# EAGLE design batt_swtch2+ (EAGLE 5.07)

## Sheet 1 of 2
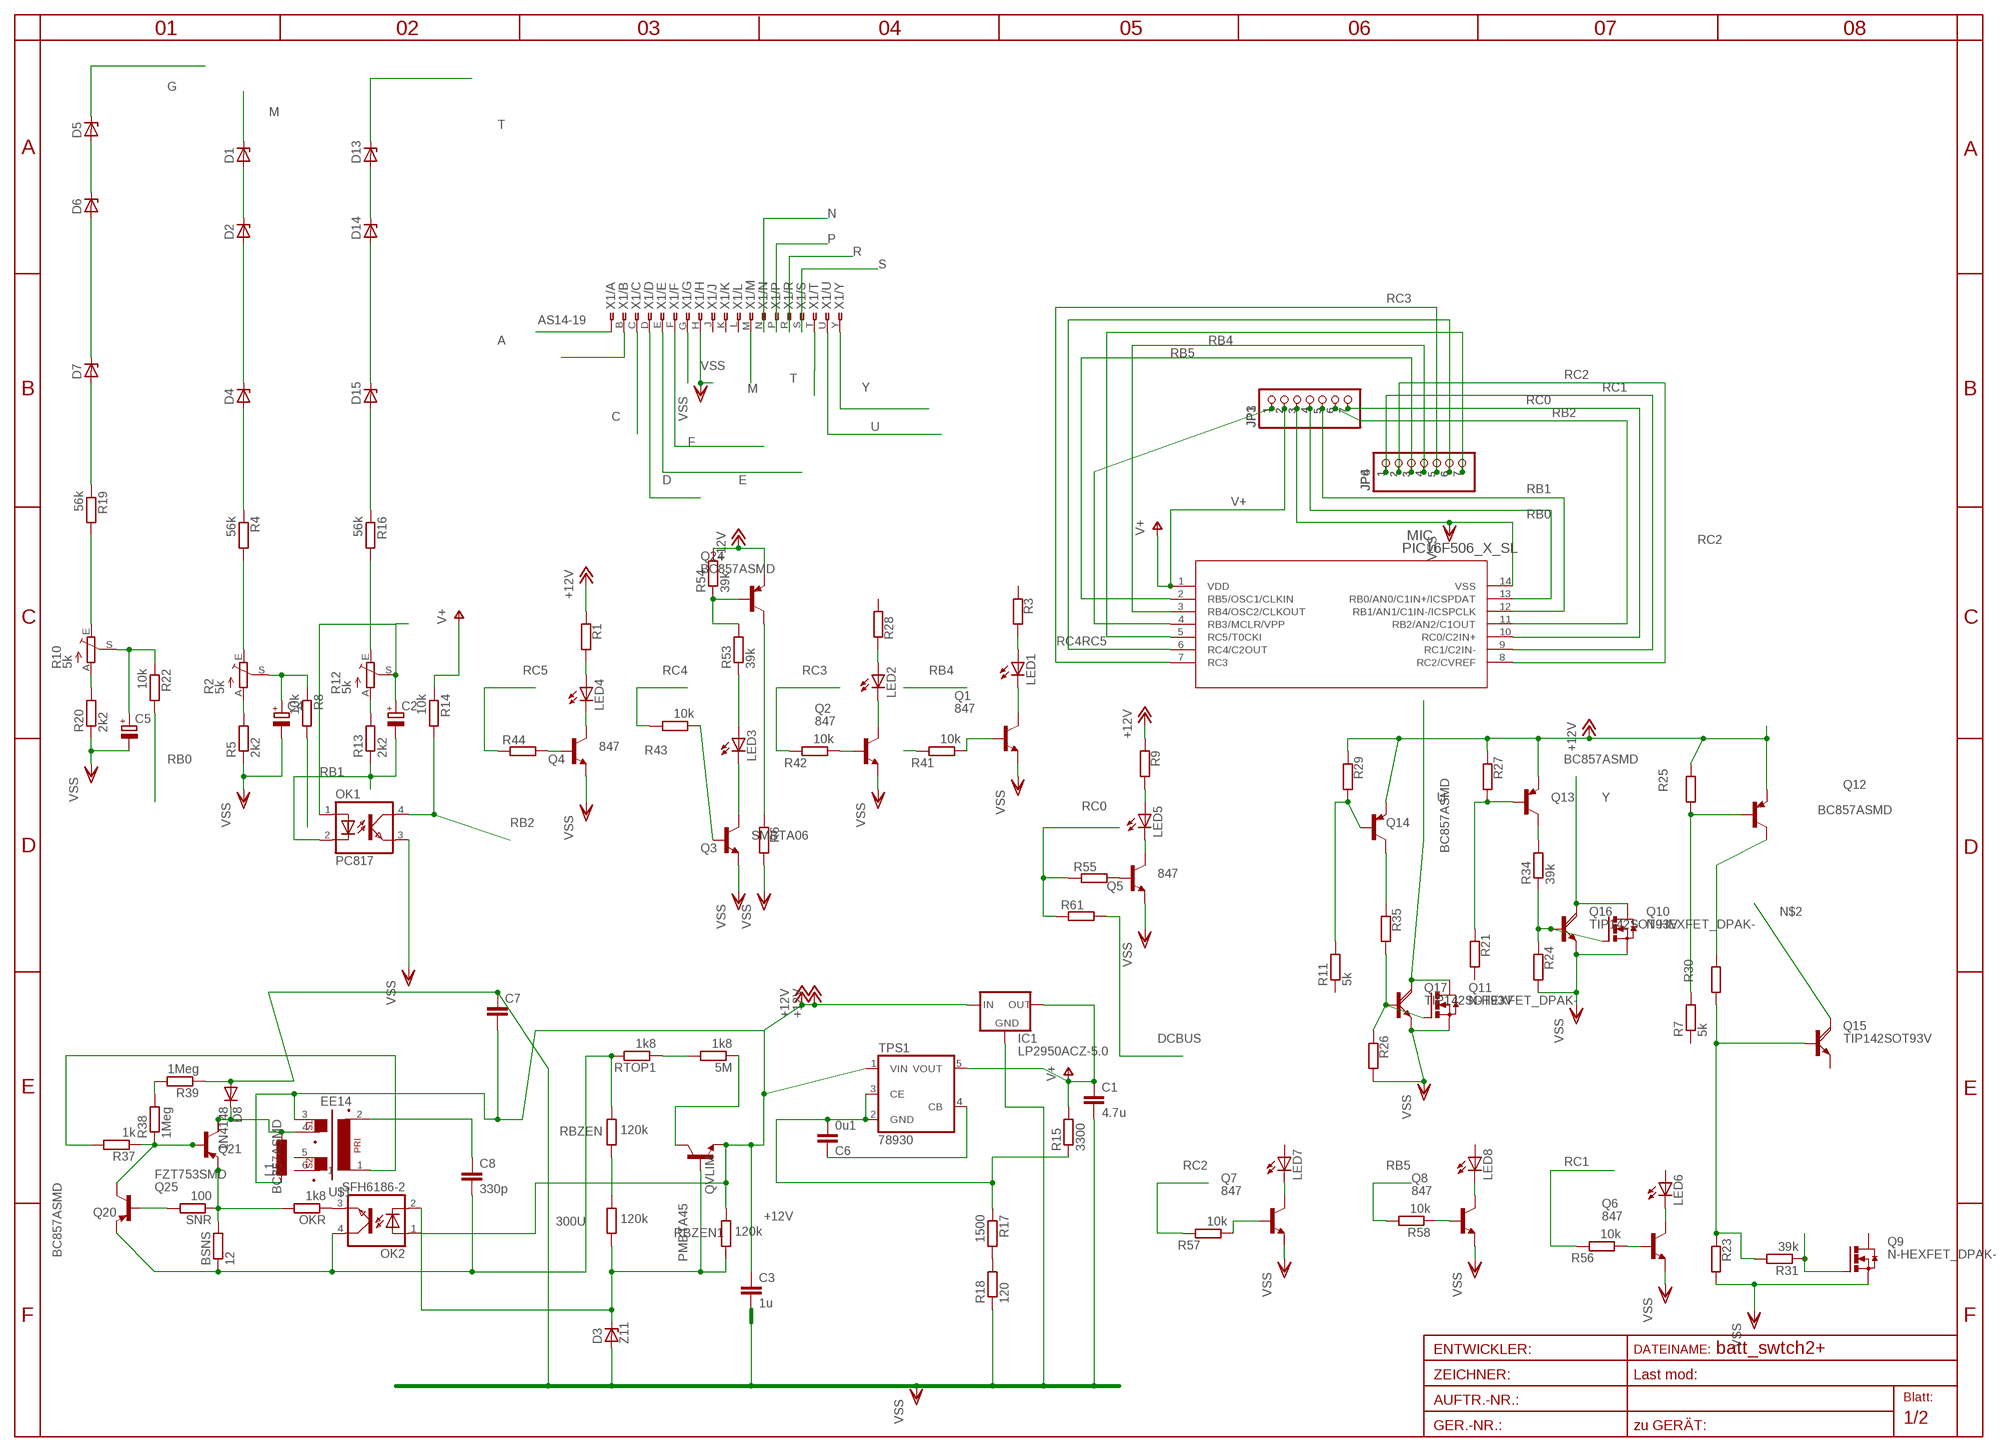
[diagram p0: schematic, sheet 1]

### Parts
5M  1k8  R-EU_R1206  [R1206]
300U  120k  R-EU_R1206  [R1206]
BSNS  12  R-EU_R0805  [R0805]
C1  4.7u  C-EUC1206  [C1206]
C2  CPOL-EUE2,5-6E  [E2,5-6E]
C3  1u  C-EUC1206  [C1206]
C4  CPOL-EUE2,5-6E  [E2,5-6E]
C5  CPOL-EUE2,5-6E  [E2,5-6E]
C6  0u1  C-EUC0805  [C0805]
C7  C-EU025-025X050  [C025-025X050]
C8  330p  C-EUC0805  [C0805]
D1  ZENER-DIODESOD80C  [SOD80C]
D2  ZENER-DIODESOD80C  [SOD80C]
D3  Z11  ZENER-DIODESOD80C  [SOD80C]
D4  ZENER-DIODESOD80C  [SOD80C]
D5  ZENER-DIODESOD80C  [SOD80C]
D6  ZENER-DIODESOD80C  [SOD80C]
D7  ZENER-DIODESOD80C  [SOD80C]
D8  1N4148  DIODE-SMA-DO214  [SMA-DO214AC]
D13  ZENER-DIODESOD80C  [SOD80C]
D14  ZENER-DIODESOD80C  [SOD80C]
D15  ZENER-DIODESOD80C  [SOD80C]
IC1  LP2950ACZ-5.0  [TO92]
JP1  PINHD-1X7  [1X07]
JP3  PINHD-1X7  [1X07]
JP4  PINHD-1X7  [1X07]
JP6  PINHD-1X7  [1X07]
L1  L-EU0204/5  [0204/5]
LED1  LEDCHIPLED_1206  [CHIPLED_1206]
LED2  LEDCHIPLED_1206  [CHIPLED_1206]
LED3  LEDCHIPLED_1206  [CHIPLED_1206]
LED4  LEDCHIPLED_1206  [CHIPLED_1206]
LED5  LEDCHIPLED_1206  [CHIPLED_1206]
LED6  LEDCHIPLED_1206  [CHIPLED_1206]
LED7  LEDCHIPLED_1206  [CHIPLED_1206]
LED8  LEDCHIPLED_1206  [CHIPLED_1206]
MIC  PIC16F506_X_SL  [SOIC14_N_MC]
OK1  PC817  [DIL04]
OK2  SFH6186-2  [SMD4]
OKR  1k8  R-EU_R0805  [R0805]
Q1  847  BC847ASMD  [SOT23]
Q2  847  BC847ASMD  [SOT23]
Q3  SMBTA06  BC847ASMD  [SOT23]
Q4  847  BC847ASMD  [SOT23]
Q5  847  BC847ASMD  [SOT23]
Q6  847  BC847ASMD  [SOT23]
Q7  847  BC847ASMD  [SOT23]
Q8  847  BC847ASMD  [SOT23]
Q9  N-HEXFET_DPAK-  [TO252]
Q10  N-HEXFET_DPAK-  [TO252]
Q11  N-HEXFET_DPAK-  [TO252]
Q12  BC857ASMD  [SOT23-BEC]
Q13  BC857ASMD  [SOT23-BEC]
Q14  BC857ASMD  [SOT23-BEC]
Q15  TIP142SOT93V  [SOT93V]
Q16  TIP142SOT93V  [SOT93V]
Q17  TIP142SOT93V  [SOT93V]
Q20  BC857ASMD  [SOT23-BEC]
Q21  BC857ASMD  [SOT23-BEC]
Q24  BC857ASMD  [SOT23-BEC]
Q25  FZT753SMD  [SOT223]
QVLIM  PMBTA45  BC847ALT1SMD  [SOT23]
R1  39k  R-EU_R0805  [R0805]
R2  5k  TRIM_EU-S64W  [S64W]
R3  39k  R-EU_R0805  [R0805]
R4  56k  R-EU_R0805  [R0805]
R5  2k2  R-EU_R0805  [R0805]
R6  39k  R-EU_R0805  [R0805]
R7  5k  R-EU_R0805  [R0805]
R8  10k  R-EU_R0805  [R0805]
R9  5k  R-EU_R0805  [R0805]
R10  5k  TRIM_EU-S64W  [S64W]
R11  5k  R-EU_R0805  [R0805]
R12  5k  TRIM_EU-S64W  [S64W]
R13  2k2  R-EU_R0805  [R0805]
R14  10k  R-EU_R0805  [R0805]
R15  3300  R-EU_R0805  [R0805]
R16  56k  R-EU_R0805  [R0805]
R17  1500  R-EU_R0805  [R0805]
R18  120  R-EU_R0805  [R0805]
R19  56k  R-EU_R0805  [R0805]
R20  2k2  R-EU_R0805  [R0805]
R21  5k  R-EU_R0805  [R0805]
R22  10k  R-EU_R0805  [R0805]
R23  39k  R-EU_R0805  [R0805]
R24  39k  R-EU_R0805  [R0805]
R25  39k  R-EU_R0805  [R0805]
R26  39k  R-EU_R0805  [R0805]
R27  39k  R-EU_R0805  [R0805]
R28  39k  R-EU_R0805  [R0805]
R29  39k  R-EU_R0805  [R0805]
R30  39k  R-EU_R0805  [R0805]
R31  39k  R-EU_R0805  [R0805]
R34  39k  R-EU_R0805  [R0805]
R35  39k  R-EU_R0805  [R0805]
R37  1k  R-EU_R0805  [R0805]
R38  1Meg  R-EU_R1206  [R1206]
R39  1Meg  R-EU_R1206  [R1206]
R41  10k  R-EU_R0805  [R0805]
R42  10k  R-EU_R0805  [R0805]
R43  10k  R-EU_R0805  [R0805]
R44  10k  R-EU_R0805  [R0805]
R53  39k  R-EU_R0805  [R0805]
R54  39k  R-EU_R0805  [R0805]
R55  10k  R-EU_R0805  [R0805]
R56  10k  R-EU_R0805  [R0805]
R57  10k  R-EU_R0805  [R0805]
R58  10k  R-EU_R0805  [R0805]
R61  10k  R-EU_R0805  [R0805]
RBZEN  120k  R-EU_R1206  [R1206]
RBZEN1  120k  R-EU_R0805  [R0805]
RTOP1  1k8  R-EU_R1206  [R1206]
SNR  100  R-EU_R1206  [R1206]
TPS1  78930  TPS78930SOT23-5  [SOT25]
U$1  EE14  [EE14]
X1  AS14-19  AS14-19OLIVE  [Y28M-19TK]

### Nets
+12V: C3.1 C7.2 IC1.3(IN) L1.2 OK2.1(A) Q12.E Q13.E Q14.E Q24.E QVLIM.2(E) R1.2 R9.2 R25.2 R27.2 R29.2 R54.2 RBZEN1.1 TPS1.1(VIN) U$1.3
A: X1.A ; also sheet 2
B1C2: Q20.C Q21.B Q25.1(B) R37.1 R38.1
BOOST_EN: Q24.C R6.2 ; also sheet 2
C: X1.C
C1: D8.K(C) L1.1 Q21.C Q25.2(C) U$1.4
CB: 300U.2 D3.C OK2.2(C) QVLIM.1(B) RBZEN1.2
D: X1.D
DCBUS: R61.1 ; also sheet 2
E: X1.E
EB: BSNS.2 OKR.2 Q21.E Q25.3(E) SNR.1
F: X1.F
G: BSNS.1 C8.2 D5.C OK2.4(COL) Q20.E RBZEN.1 RTOP1.2 X1.G ; also sheet 2
GND1: C6.1 TPS1.4(CB)
M: D1.C X1.M
N: X1.N
N$1: 300U.1 RBZEN.2
N$2: Q15.C
N$3: OK2.3(EMIT) OKR.1
N$4: Q8.1(B) R58.1
N$5: C2.+ OK1.1(A) R12.S
N$6: Q3.1(B) R43.1
N$7: LED6.C Q6.3(C)
N$8: R17.2 R18.2
N$9: R41.2
N$10: LED8.C Q8.3(C)
N$11: Q2.1(B) R42.1
N$12: Q1.1(B) R41.1
N$14: Q5.1(B) R55.1
N$16: 5M.1 QVLIM.3(C)
N$17: LED7.C Q7.3(C)
N$18: D15.A R16.1
N$19: LED1.C Q1.3(C)
N$20: LED1.A R3.1
N$21: Q14.B R11.2 R29.1
N$22: LED2.C Q2.3(C)
N$23: D14.A D15.C
N$24: D13.A D14.C
N$25: LED2.A R28.1
N$26: R12.A R13.2
N$28: Q6.1(B) R56.1
N$29: 5M.2 RTOP1.1
N$30: Q4.1(B) R44.1
N$31: Q7.1(B) R57.1
N$32: LED3.C Q3.3(C)
N$33: LED4.C Q4.3(C)
N$34: D7.A R19.1
N$35: D6.A D7.C
N$36: LED4.A R1.1
N$37: Q12.C R30.2
N$38: D5.A D6.C
N$39: R10.E R19.2
N$40: R10.A R20.2
N$41: D4.A R4.1
N$42: D2.A D4.C
N$43: D1.A D2.C
N$44: R2.E R4.2
N$45: R2.A R5.2
N$46: C4.+ R2.S R8.1
N$47: LED5.A R9.1
N$48: C5.+ R10.S R22.1
N$49: Q14.C R35.2
N$50: Q15.B R23.2 R30.1 R31.2
N$51: Q10.1(G) Q16.B R24.2 R34.1
N$52: LED5.C Q5.3(C)
N$53: Q12.B R7.2 R25.1
N$54: Q9.1(G) R31.1
N$55: Q13.B R21.2 R27.1
N$57: Q13.C R34.2
N$59: Q11.1(G) Q17.B R26.2 R35.1
N$60: R37.2 U$1.1
N$61: C8.1 U$1.2
N$62: R38.2 R39.2
N$63: Q20.B SNR.2
N$65: R12.E R16.2
N$81: Q24.B R53.2 R54.1
N$82: LED3.A R53.1
P: X1.P
R: X1.R
RB0: JP1.4 JP3.4 MIC.13(RB0/AN0/C1IN+/ICSPDAT) R22.2
RB1: JP1.5 JP3.5 MIC.12(RB1/AN1/C1IN-/ICSPCLK) R8.2
RB2: JP1.6 JP3.6 MIC.11(RB2/AN2/C1OUT) OK1.4(COL) R14.2
RB4: JP4.4 JP6.4 MIC.3(RB4/OSC2/CLKOUT)
RB5: JP4.3 JP6.3 MIC.2(RB5/OSC1/CLKIN) R58.2
RC0: JP1.7 JP3.7 MIC.10(RC0/C2IN+) R55.2 R61.2
RC1: JP4.1 JP6.1 MIC.9(RC1/C2IN-) R56.2
RC2: JP4.2 JP6.2 MIC.8(RC2/CVREF) R57.2
RC3: JP4.5 JP6.5 MIC.7(RC3) R42.2
RC4: JP4.6 JP6.6 MIC.6(RC4/C2OUT) R43.2
RC5: JP4.7 JP6.7 MIC.5(RC5/T0CKI) R44.2
S: C2.- OK1.2(C) R13.1 X1.S
T: D13.C X1.T
U: Q11.3(D) Q17.C X1.U
V+: C1.1 IC1.1(OUT) JP1.2 JP3.2 MIC.1(VDD) R14.1 R15.2 TPS1.5(VOUT)
V-: C6.2 R15.1 R17.1 TPS1.2(GND) TPS1.3(CE)
VSS: C1.2 C3.2 C4.- C5.- C7.1 D3.A D8.A IC1.2(GND) JP1.3 JP3.3 MIC.14(VSS) OK1.3(EMIT) Q1.2(E) Q2.2(E) Q3.2(E) Q4.2(E) Q5.2(E) Q6.2(E) Q7.2(E) Q8.2(E) Q9.2(S) Q10.2(S) Q11.2(S) Q16.E Q17.E R5.1 R6.1 R18.1 R20.1 R23.1 R24.1 R26.1 R39.1 X1.B X1.H ; also sheet 2
WIND: JP1.1 JP3.1 MIC.4(RB3/MCLR/VPP)
Y: Q10.3(D) Q16.C X1.Y
Unconnected: LED6.A LED7.A LED8.A Q9.3(D) Q15.E Q25.4(C/) R3.2 R7.1 R11.1 R21.1 R28.2 U$1.5 U$1.6 X1.J X1.K X1.L

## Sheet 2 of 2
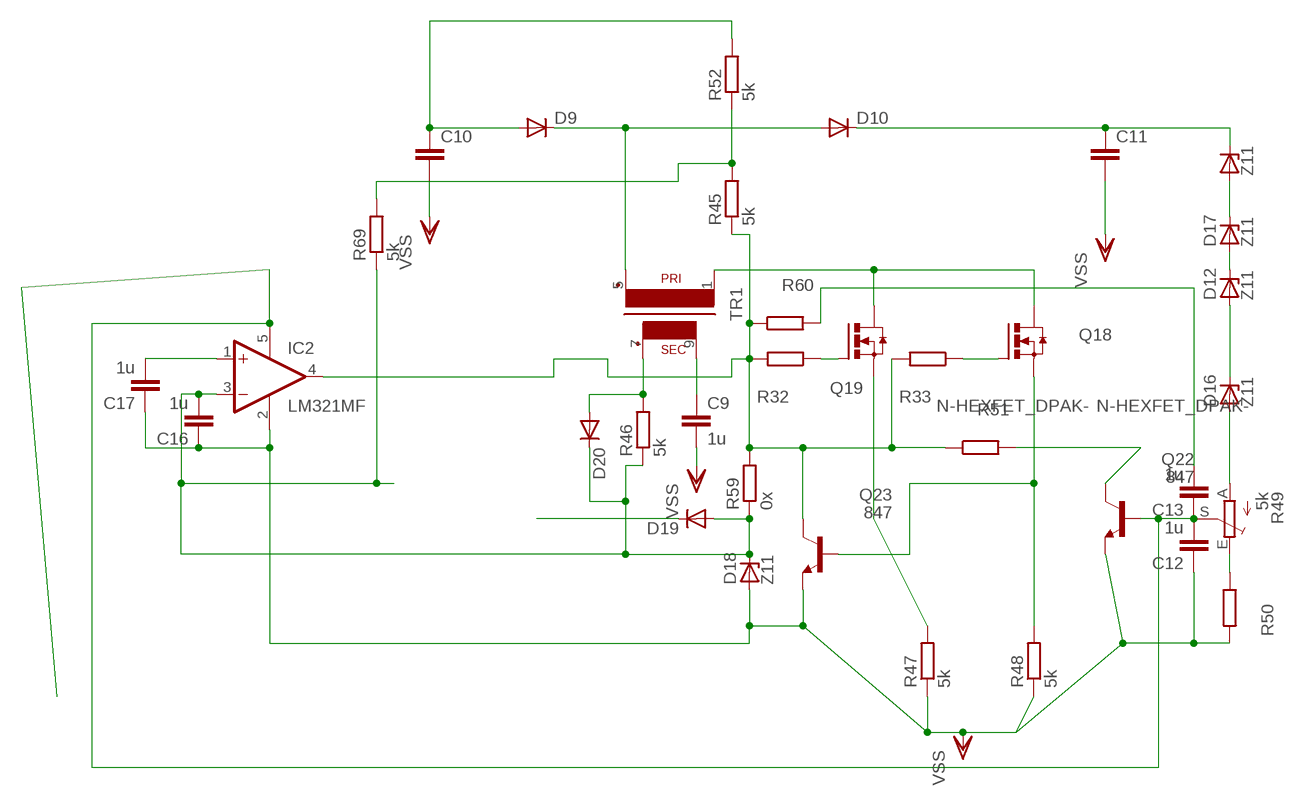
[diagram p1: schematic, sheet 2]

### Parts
C9  1u  C-EUC1206  [C1206]
C10  C-EU075-052X106  [C075-052X106]
C11  C-EU075-052X106  [C075-052X106]
C12  1u  C-EUC1206  [C1206]
C13  1u  C-EUC1206  [C1206]
C16  1u  C-EUC0805  [C0805]
C17  1u  C-EUC0805  [C0805]
D9  DIODE-SMC  [SMC]
D10  DIODE-SMC  [SMC]
D11  Z11  ZENER-DIODESOD80C  [SOD80C]
D12  Z11  ZENER-DIODESOD80C  [SOD80C]
D16  Z11  ZENER-DIODESOD80C  [SOD80C]
D17  Z11  ZENER-DIODESOD80C  [SOD80C]
D18  Z11  ZENER-DIODESOD80C  [SOD80C]
D19  DIODE-MINIMELF  [MINIMELF]
D20  DIODE-MINIMELF  [MINIMELF]
IC2  LM321MF  [SOT23-5]
Q18  N-HEXFET_DPAK-  [TO252]
Q19  N-HEXFET_DPAK-  [TO252]
Q22  847  BC847ASMD  [SOT23]
Q23  847  BC847ASMD  [SOT23]
R32  39k  R-EU_R0805  [R0805]
R33  39k  R-EU_R0805  [R0805]
R45  5k  R-EU_R1206  [R1206]
R46  5k  R-EU_R0805  [R0805]
R47  5k  R-EU_R2010  [R2010]
R48  5k  R-EU_R2010  [R2010]
R49  5k  TRIM_EU-S64W  [S64W]
R50  39k  R-EU_R0805  [R0805]
R51  39k  R-EU_R0805  [R0805]
R52  5k  R-EU_R1206  [R1206]
R59  0x  R-EU_R0402  [R0402]
R60  39k  R-EU_R0805  [R0805]
R69  5k  R-EU_0207/22  [0207/22]
TR1  VR11  [1X3WDIRVER]

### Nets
A: C11.1 D10.C D11.C ; also sheet 1
BOOST_EN: D19.C ; also sheet 1
DCBUS: C12.2 C13.1 IC2.5(V+) Q22.1(B) R49.S ; also sheet 1
G: C10.1 D9.A R52.2 ; also sheet 1
N$13: D9.C D10.A TR1.5(P2)
N$15: Q18.3(D) Q19.3(D) TR1.1
N$27: C16.2 D18.C D19.A D20.C IC2.3(-IN) R46.1 R59.1 R69.1
N$56: Q18.1(G) R33.1
N$58: Q19.1(G) R32.1
N$64: D20.A R46.2 TR1.7(S3)
N$66: IC2.4(OUT) Q23.3(C) R32.2 R33.2 R45.1 R51.1 R59.2 R60.1
N$67: C13.2 R60.2
N$68: Q19.2(S) R47.2
N$71: Q22.3(C) R51.2
N$72: Q18.2(S) Q23.1(B) R48.2
N$73: D16.A R49.A
N$74: C9.1 TR1.9(S4)
N$76: D12.A D16.C
N$77: D12.C D17.A
N$78: R49.E R50.1
N$79: D11.A D17.C
N$80: R45.2 R52.1 R69.2
N$96: C17.2 IC2.1(+IN)
VSS: C9.2 C10.2 C11.2 C12.1 C16.1 C17.1 D18.A IC2.2(V-) Q22.2(E) Q23.2(E) R47.1 R48.1 R50.2 ; also sheet 1

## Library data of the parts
5M 300U BSNS OKR R4 R5 R8 R13-R20 R22 R37-R39 RBZEN RBZEN1 RTOP1 SNR = rcl:R-EU_: RESISTOR, European symbol
C1 C3 C6-C13 C16 C17 = rcl:C-EU: CAPACITOR, European symbol
C2 C4 C5 = rcl:CPOL-EU: POLARIZED CAPACITOR, European symbol
D1-D7 D11-D18 = diode:ZENER-DIODE: Z-Diode
D8-D10 D19 D20 = diode:DIODE-: DIODE
IC1 = v-reg:LP2950?*: Source: http://cache.national.com/ds/LP/LP2950.pdf
IC2 = linear:LM321?*: Low Power Single Op Amp Source: http://cache.national.com/ds/LM/LM321.pdf
JP1 JP3 JP4 JP6 = pinhead:PINHD-1X7: PIN HEADER
L1 = rcl:L-EU: INDUCTOR, European symbol
LED1-LED8 = led:LED: LED
MIC = pic16f506mc:PIC16F506_X_SL
OK1 = optocoupler:PC817: SHARP OPTO COUPLER
OK2 = optocoupler:SFH618?*: Optocoupler, Phototransistor Output, Low Input Current Source: http://www.vishay.com/docs/83673/sfh618.pdf
Q1-Q8 Q22 Q23 QVLIM = transistor-npn:BC847*: NPN Transistor
Q9-Q11 Q18 Q19 = transistor-power:N-HEXFET_?-*: HEXFET® Power MOSFET
Q12-Q14 Q20 Q21 Q24 = transistor-pnp:BC857*: PNP Transistror
Q15-Q17 = transistor-power:TIP142: NPN DARLINGTON TRANSISTOR
Q25 = transistor-pnp:FZT753SMD: PNP Transistor
R1 R3 R6 R7 R9 R11 R21 R23-R35 R41-R48 R50-R61 R69 = rcl-2:R-EU_: RESISTOR, European symbol
R2 R10 R12 R49 = pot:TRIM_EU-: POTENTIOMETER
TPS1 = v-reg:TPS78930
TR1 = trafo:VR11: TRANSFORMER 1 primary winding, 1 secondary winding BLOCK
U$1 = trafo:EE14
X1 = con-deutsch:AS14-19: DEUTSCH Connector

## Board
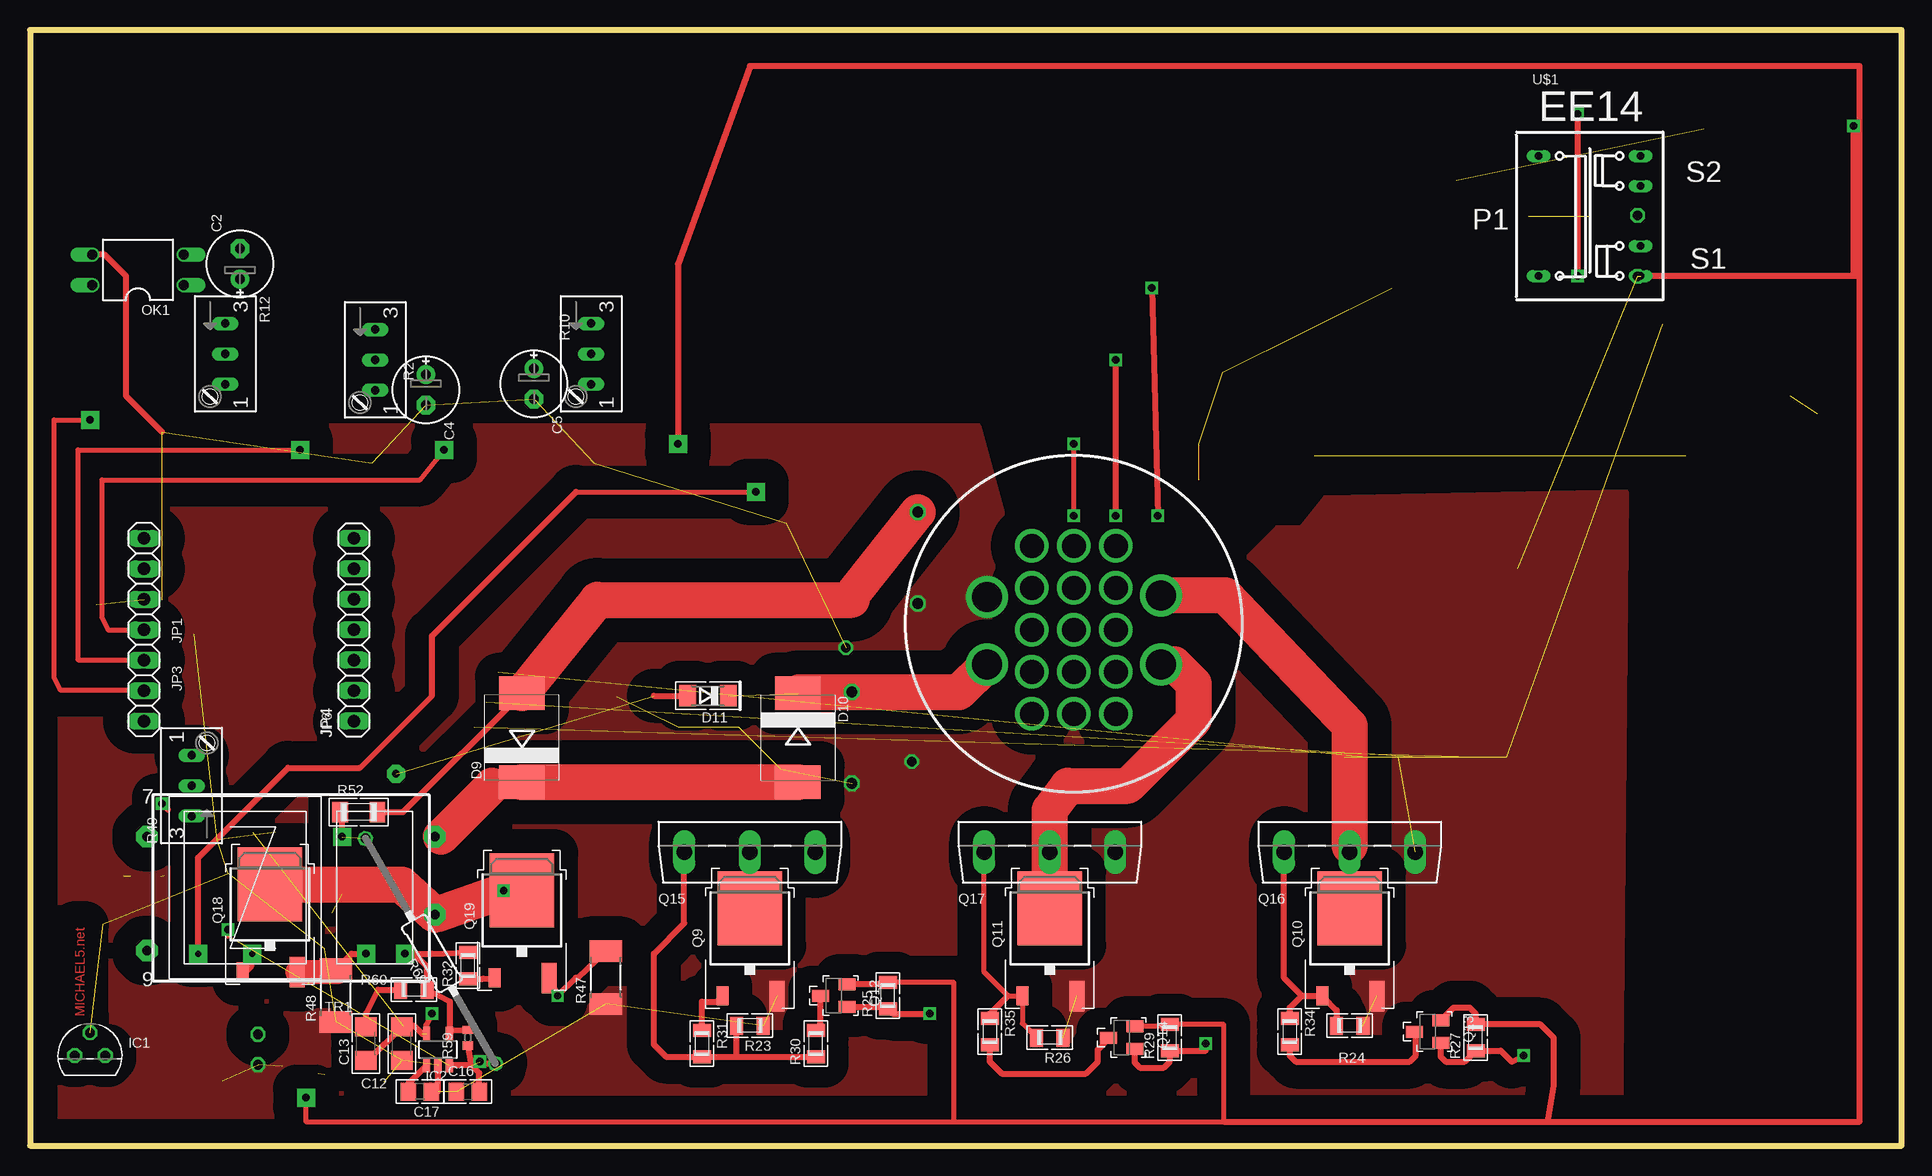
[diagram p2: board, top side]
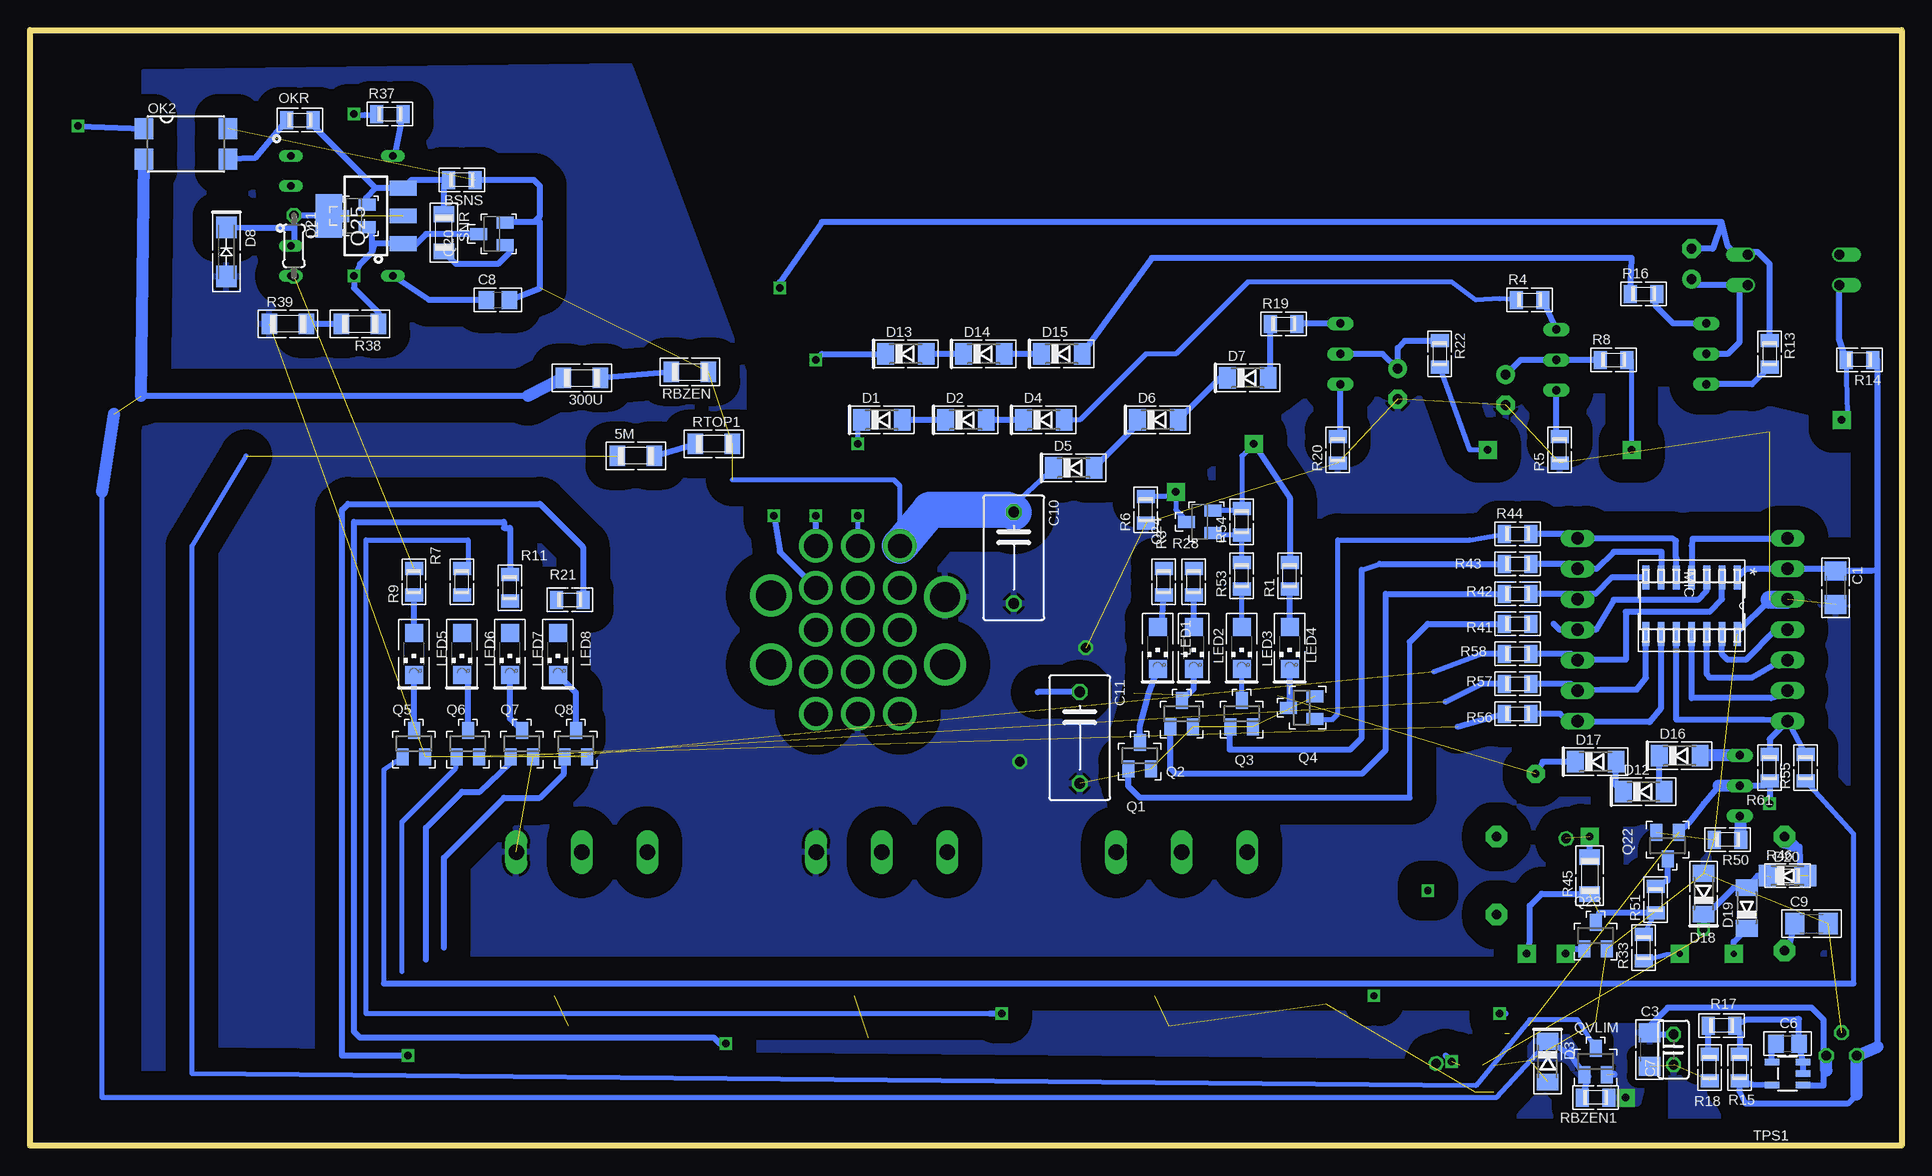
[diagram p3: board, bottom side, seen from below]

Size 156 x 93 mm. Coordinates in mm from the lower left corner, seen from the top.
Outline: 156,0 156,93 0,93 0,0 156,0
Copper layers (1*16): Top 0.035mm / dielectric 1.5mm / Bottom 0.035mm
Design rules "default *": minimum track width 40mil, minimum drill 30mil, track to track 8mil, track to pad 8mil, pad to pad 8mil, via to via 8mil, smd to smd 8mil, copper to edge 40mil, drill to drill 8mil, minimum pad ring 8mil, minimum via ring 8mil, stop-mask expansion 4mil, vias tented up to drill 0mil, thermal gap 10mil

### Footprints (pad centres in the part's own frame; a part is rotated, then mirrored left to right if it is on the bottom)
R1206 = smd 1.3 x 1.7: 1 -1.55,0; 2 1.55,0
R0805 = smd 1.1 x 1.5: 1 -1.1,0; 2 1.1,0
C1206 = smd 1.6 x 1.8: 1 -1.4,0; 2 1.4,0
E2,5-6E = drill 0.813 pad 1.575 round: + -1.27,0 | drill 0.813 pad 1.575 octagon: - 1.27,0
C0805 = smd 1.3 x 1.5: 1 -0.95,0; 2 0.95,0
C025-025X050 = drill 0.813 octagon: 1 -1.27,0; 2 1.27,0
C075-052X106 = drill 0.914 octagon: 1 -3.81,0; 2 3.81,0
SOD80C = smd 1.4 x 1.8: A 1.7,0; C -1.7,0
SMA-DO214AC = smd 1.8 x 1.7: A 2.05,-0.127; K -2.05,-0.127
SMC = smd 2.8 x 3.8: A 3.7,0; C -3.7,0
MINIMELF = smd 1.4 x 1.8: A 1.7,0; C -1.7,0
TO92 = drill 0.813 octagon: 1 -1.27,0; 2 0,1.905; 3 1.27,0
SOT23-5 = smd 0.6 x 1.2: 1 -0.95,-1.306; 2 0,-1.306; 3 0.95,-1.306; 4 0.95,1.306; 5 -0.95,1.306
1X07 = drill 1.016 long: 1 -7.62,0; 2 -5.08,0; 3 -2.54,0; 4 0,0; 5 2.54,0; 6 5.08,0; 7 7.62,0
0204/5 = drill 0.813 octagon: 1 -2.54,0; 2 2.54,0
CHIPLED_1206 = smd 1.5 x 1.5: A 0,-1.75; C 0,1.75
SOIC14_N_MC = smd 1.981 x 0.559: 1 -2.362,3.81; 2 -2.362,2.54; 3 -2.362,1.27; 4 -2.362,0; 5 -2.362,-1.27; 6 -2.362,-2.54; 7 -2.362,-3.81; 8 2.362,-3.81; 9 2.362,-2.54; 10 2.362,-1.27; 11 2.362,0; 12 2.362,1.27; 13 2.362,2.54; 14 2.362,3.81
DIL04 = drill 0.813 offset: 1 -1.27,-3.81; 2 1.27,-3.81; 3 1.27,3.81; 4 -1.27,3.81
SMD4 = smd 1.78 x 1.55: 1 -1.27,-3.5; 2 1.27,-3.5; 3 1.27,3.5; 4 -1.27,3.5
SOT23 = smd 1 x 1.4: 1 -0.95,-1.1; 2 0.95,-1.1; 3 0,1.1
TO252 = smd 1 x 1.6: 1 -2.28,-3.53 | smd 1.27 x 2.54: 2 2.28,-3.53 | smd 5.4 x 6.2: 3 0,3.77
SOT23-BEC = smd 1 x 1.4: B -0.95,-1.1; C 0,1.1; E 0.95,-1.1
SOT93V = drill 1.3 pad 1.676 long: B -5.461,-2.54; C 0,-2.54; E 5.461,-2.54
SOT223 = smd 1.219 x 2.235: 1 -2.311,-3.099; 2 0,-3.099; 3 2.311,-3.099 | smd 3.6 x 2.2: 4 0,3.099
S64W = drill 0.7 long: A 2.54,1.27; E -2.54,1.27; S 0,1.27
R2010 = smd 1.8 x 2.7: 1 -2.2,0; 2 2.2,0
R0402 = smd 0.7 x 0.9: 1 -0.65,0; 2 0.65,0
0207/22 = drill 0.813 octagon: 1 -10.58,0; 2 11.08,0
SOT25 = smd 0.55 x 1.2: 1 -0.95,-1.3; 2 0,-1.3; 3 0.95,-1.3; 4 0.95,1.3; 5 -0.95,1.3
1X3WDIRVER = drill 0.8 pad 1.778 octagon: 1 -12,2.25; 5 -12,-4.25; 7 12,-4.25; 9 12,5.25
EE14 = drill 0.6 pad 1 long: 1 4.25,-5; 2 4.25,5; 3 -4.25,5 | drill 0.6 pad 1.016 long: 4 -4.25,2.5; 5 -4.25,-2.5; 6 -4.25,-5
Y28M-19TK = drill 2.5 pad 3.5 round: A -7.25,-2.875; B -7.25,2.75; U 7.25,-2.875; Y 7.25,2.875 | drill 2 pad 2.54 round: C -3.5,-7; D -3.5,-3.5; E -3.5,0; F -3.5,3.5; G -3.5,7; H 0,-7; J 0,-3.5; K 0,0; L 0,3.5; M 0,7; N 3.5,-7; P 3.5,-3.5; R 3.5,0; S 3.5,3.5; T 3.5,7

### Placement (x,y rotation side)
5M  105.5,57.5 0 bottom
300U  110,64 180 bottom
BSNS  120,80.5 180 bottom
C1  5.5,46.5 270 bottom
C2  17.5,73.5 90 top
C3  21,8 270 bottom
C4  33,63 270 top
C5  42,63.5 270 top
C6  9.5,8.5 0 bottom
C7  19,8 90 bottom
C8  117,70.5 0 bottom
C9  7.5,18.5 0 bottom
C10  74,49 270 bottom
C11  68.5,34 270 bottom
C12  31,8.5 90 top
C13  28,8.5 90 top
C16  36.5,4.5 0 top
C17  32.5,4.5 180 top
D1  85,60.5 0 bottom
D2  78,60.5 0 bottom
D3  29.5,7 270 bottom
D4  71.5,60.5 0 bottom
D5  69,56.5 0 bottom
D6  62,60.5 0 bottom
D7  54.5,64 0 bottom
D8  139.5,74.5 270 bottom
D9  41,34 90 top
D10  64,34 270 top
D11  56.5,37.5 180 top
D12  21.5,29.5 0 bottom
D13  83,66 0 bottom
D14  76.5,66 0 bottom
D15  70,66 0 bottom
D16  18.5,32.5 0 bottom
D17  25.5,32 0 bottom
D18  16.5,21 90 bottom
D19  12.9,19.8 90 bottom
D20  9.5,22.5 0 bottom
IC1  5,7.5 0 top
IC2  34,8 0 top
JP1  9.5,43 270 top
JP3  9.5,43 270 top
JP4  27,43 90 top
JP6  27,43 90 top
L1  134,75 270 bottom
LED1  62,41.5 180 bottom
LED2  59,41.5 180 bottom
LED3  55,41.5 180 bottom
LED4  51,41.5 180 bottom
LED5  124,41 180 bottom
LED6  120,41 180 bottom
LED7  116,41 180 bottom
LED8  112,41 180 bottom
MIC  17.5,45 270 bottom
OK1  9,73 90 top
OK2  143,83.5 270 bottom
OKR  133.5,85.5 0 bottom
Q1  63.5,32.5 0 bottom
Q2  60,36 0 bottom
Q3  55,36 0 bottom
Q4  50,36.5 90 bottom
Q5  124,33.5 0 bottom
Q6  119.5,33.5 0 bottom
Q7  115,33.5 0 bottom
Q8  110.5,33.5 0 bottom
Q9  60,16 0 top
Q10  110,16 0 top
Q11  85,16 0 top
Q12  67,12.5 90 top
Q13  116.5,9.5 90 top
Q14  91,9 90 top
Q15  60,27 0 top
Q16  110,27 0 top
Q17  85,27 0 top
Q18  20,18 0 top
Q19  41,17.5 0 top
Q20  117.5,76 90 bottom
Q21  129,77.5 90 bottom
Q22  19.5,25 180 bottom
Q23  25.5,17.5 0 bottom
Q24  58.5,52 90 bottom
Q25  128,77.5 90 bottom
QVLIM  25.5,7 0 bottom
R1  51,47.5 90 bottom
R2  27.5,65.5 270 top
R3  61.5,47 90 bottom
R4  31,70.5 0 bottom
R5  28.5,58 90 bottom
R6  63,53 90 bottom
R7  120,47 90 bottom
R8  24,65.5 0 bottom
R9  124,47 90 bottom
R10  45.5,66 270 top
R11  116,46.5 90 bottom
R12  15,66 270 top
R13  11,66 270 bottom
R14  3.5,65.5 180 bottom
R15  13.5,6.5 270 bottom
R16  21.5,71 0 bottom
R17  15,10 180 bottom
R18  16,6.5 90 bottom
R19  51.5,68.5 0 bottom
R20  47,58 90 bottom
R21  111,45.5 0 bottom
R22  38.5,66 270 bottom
R23  60,10 180 top
R24  110,10 180 top
R25  71.5,12.5 90 top
R26  85,9 180 top
R27  120.5,9 90 top
R28  59,47 90 bottom
R29  95,9 90 top
R30  65.5,8.5 90 top
R31  56,8.5 270 top
R32  36.5,15 90 top
R33  21.5,16.5 90 bottom
R34  105,9.5 270 top
R35  80,9.5 270 top
R37  126,86 0 bottom
R38  128.5,68.5 180 bottom
R39  134.5,68.5 0 bottom
R41  32,43.5 0 bottom
R42  32,46 0 bottom
R43  32,48.5 0 bottom
R44  32,51 0 bottom
R45  26,22.5 90 bottom
R46  9.5,22.5 0 bottom
R47  48,14 90 top
R48  25.5,12.5 90 top
R49  14.75,30 90 top
R50  14.5,25.5 180 bottom
R51  20.5,20.5 90 bottom
R52  27.4,27.8 0 top
R53  55,47.5 90 bottom
R54  55,52 90 bottom
R55  8,31.5 90 bottom
R56  32,36 0 bottom
R57  32,38.5 0 bottom
R58  32,41 0 bottom
R59  36.5,9 90 top
R60  32,13 180 top
R61  11,31.5 90 bottom
R69  33.5,16 120 top
RBZEN  101,64.5 180 bottom
RBZEN1  25.5,4 180 bottom
RTOP1  99,58.5 0 bottom
SNR  121.5,76.1 270 bottom
TPS1  9.5,6 90 bottom
TR1  21.75,21.5 180 top
U$1  130,77.5 180 top
X1  87,43 0 top

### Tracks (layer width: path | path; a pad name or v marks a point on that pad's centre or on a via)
+12V  (via drill 0.6, 0.6 pad 1.5)  (3 unrouted)
  Top 0.406: Q14.E 95,9.95 R29.2 99.5,10.1 99.5,2 77,2 | 77,2 23,2 v23,4 | R25.2 77,13.6 77,2
  Top 0.5: v54,58.5 54,73.5 60,90 152.5,90 152.5,72.5 | Q12.E 71.35,13.45 R25.2 | 126.5,2 127,5 127,9 125.9,10.1 R27.2 120.5,11 120,11.5 118.65,11.5 Q13.E | 99.5,2 126.5,2 | 126.5,2 152.5,2 152.5,72.5 | 152.46,72.46 L1.2 | 152.5,72.5 152.46,72.46 | v152,85 152,72.5 152.46,72.46
  Bottom 0.406: Q24.E 55.15,52.95 R54.2 55,57.5 54.08,58.42 54.08,58.6 51,54
  Bottom 0.5: 6.5,6 6.5,5 8.15,5 TPS1.1 | 6.5,6 6.5,10.5 7.5,11.5 19.5,11.5 21,10 C3.1 21,9 20.73,9.27 C7.2 | 6.5,6 6.27,6.23 | v54,58.5 51,54 R1.2 | 24,6 23.9,5.9 | v152,85 OK2.1
  Bottom 1: 6.27,6.23 IC1.3
  pour Bottom (isolate 1, rank 3): 24,3.5 24,10 20.5,10 21,7.5 22,3.5
A  (1 unrouted)
  Top 0.5: D10.C 64.11,37.81
  Top 3: X1.A 77.44,37.81 C11.1 64.11,37.81
  Bottom 0.5: C11.1 71.99,37.81
B1C2  (via drill 0.6)
  Top 0.5: v129,72.5 v129,86
  Bottom 0.5: Q20.C 123,76 124,75 124.71,75 Q25.1 127.31,75.19 127.5,74.5 | R37.1 128.1,85.9 v129,86 | 127.5,74.5 128.5,73.5 v129,72.5 129,71.5 126.95,69.45 R38.1 | 127.5,74.5 127.5,76.15 Q21.B
BOOST_EN  (via drill 0.5 pad 1.5, 0.6 pad 1.5)
  Top 0.4: 27.5,31.5 33.5,37.5
  Top 0.406: 45.5,54.5 v60.5,54.5
  Top 0.5: 45.5,54.5 33.5,42.5 33.5,37.5 | 27.5,31.5 21.5,31.5 14,24 v14,16
  Bottom 0.406: 60.5,54.1 R6.2 | v60.5,54.5 60.5,54.1 | Q24.C 59.6,52.1 60.5,53 60.5,54.1
  Bottom 0.5: D19.C 14,17 v14,16
C1  (1 unrouted)
  Bottom 0.5: U$1.4 134,75.25 134,76.5 | 134,76.5 L1.1 130.14,77.54 Q21.C | D8.K 138.08,76.5 134,76.5
CB  (1 unrouted)
  Bottom 0.406: 150,54.5 150,4 33.8,4 D3.C
  Bottom 0.5: D3.C 27.8,7.7 27.5,8 27.5,7.45 QVLIM.1 26.1,5.75 RBZEN1.2 | 114.5,62.5 146.73,62.5
  Bottom 1: 300U.2 114.5,62.5 | 150,54.5 149,61 | 146.73,62.5 OK2.2
  pour Bottom (isolate 1, rank 3): 26,10 30.5,10 31,9.5 31,7.5 30.5,7 28,7 26.5,5.5 26,5.5 25.5,6 25.5,9.5
DCBUS  (via drill 0.6)  (2 unrouted)
  Top 0.5: 32.69,9.31 32,10 31.1,10 C12.2 28.2,7.1 C13.1 | IC2.5 33.05,10.05 v33.5,11 | v11,28.5 11.5,28
  Bottom 0.5: 15.23,30 16.5,28.5 17.65,27 Q22.1 | v33.5,11 33,11 | v11,28.5 R61.1 11.4,30 R49.S
  Bottom 1: R49.S 15.23,30
EB
  Bottom 0.5: SNR.1 121.5,80.1 BSNS.2 124.21,80.5 Q25.3 127.19,79.81 | 127.19,79.81 128,79 128,78.55 Q21.E | OKR.2 132.4,85.02 127.19,79.81
G  (4 unrouted)
  Top 0.5: 68.5,45.5 68.49,45.8 | R52.2 31.1,27.8 D9.A
  Top 3: D9.A 47.3,45.5 68.5,45.5 | 68.49,45.8 C10.1
  Bottom 0.406: 74.5,53 D5.C | X1.G 83.5,55 84,55.5 97.45,55.5
  Bottom 0.5: C8.2 113.5,71.5 113.5,77 114,77 | 114,77 116.85,77 Q20.E | BSNS.1 114,80.5 113.5,80 113.5,77.5 114,77
  Bottom 3: X1.G 81,53 74.5,53 C10.1
GND1
  Bottom 0.5: TPS1.4 10.8,8.15 C6.1
M  (via drill 0.6)
  Top 0.406: v87,52.5 v87,58.5
  Bottom 0.406: X1.M v87,52.5 | v87,58.5 87,60.2 D1.C
N$1
  Bottom 0.5: RBZEN.2 300U.1
N$3
  Bottom 0.5: OK2.3 137.23,82.32 OKR.1
N$4  (1 unrouted)
  Bottom 0.406: 35,41 39,39.5
  Bottom 0.5: Q8.1 111.5,32.35 111.5,31 113.5,29 116.5,29 121.5,24 121.5,16.5 | R58.1 35,41
N$5
  Bottom 0.5: 14,71.73 OK1.1 | 14,71.73 17,71.73 C2.+ | R12.S 14.5,66 13.5,67 13.5,71.23 14,71.73
N$6
  Bottom 0.406: 45,48 43.5,48.5
  Bottom 0.5: 43.5,48.5 R43.1 | 45,48 45,34 46,33 56,33 56,33.85 Q3.1
N$7
  Bottom 0.5: Q6.3 119.5,38.75 LED6.C
N$8
  Bottom 0.5: R17.2 16.1,8 R18.2
N$10
  Bottom 0.5: Q8.3 110.5,37.75 LED8.C
N$11
  Bottom 0.5: Q2.1 60.95,31.45 60.5,31 45,31 43,33 43,46 R42.1
N$12
  Bottom 0.406: 41,29 41,42
  Bottom 0.5: Q1.1 64.45,29.95 63.5,29 41,29 | 41,42 39.5,43.5 R41.1
N$13
  Top 0.5: TR1.5 34.25,25.75 | 38.5,30 40.7,30 D9.C
  Top 3: 34.25,25.75 38.5,30 | D9.C D10.A
N$14
  Bottom 0.406: R55.1 4,26 4,13.5 | 126.5,13.5 126.5,31.35 Q5.1
  Bottom 0.5: 4,13.5 126.5,13.5
N$15  (via drill 0.6)
  Top 0.5: v39.48,21.25 Q19.3
  Top 3: Q18.3 30.98,21.77 TR1.1 v39.48,21.25
N$16  (1 unrouted)
  Bottom 0.406: 138,57.5 142.5,50 142.5,6 35.5,5 31,10.5 27,10.5 QVLIM.3
N$17
  Bottom 0.5: LED7.C 116,35.6 Q7.3
N$18
  Bottom 0.5: R16.1 22.5,74 62.5,74 D15.A
N$19
  Bottom 0.5: LED1.C 62.75,37.75 63.5,35 Q1.3
N$20
  Bottom 0.5: LED1.A 61.65,43.75 R3.1
N$21  (via drill 0.6)
  Top 0.5: v98,8.5 98,7.9 R29.1 95,7 94.5,6.5 92.5,6.5 92.1,6.9 Q14.B
  Bottom 0.5: R11.2 116,51.5 116.5,51.5 116.5,52 129,52 129,9.5 128.5,9 99,9 98.5,8.5 v98,8.5
N$22
  Bottom 0.5: LED2.C 59,38.1 Q2.3
N$23
  Bottom 0.5: D15.C D14.A
N$24
  Bottom 0.5: D14.C D13.A
N$25
  Bottom 0.5: LED2.A R28.1
N$26
  Bottom 0.5: R12.A 12.44,63.46 R13.2
N$27  (via drill 0.6)  (3 unrouted)
  Top 0.5: 36.79,6.69 IC2.3 | 36.79,6.69 R59.1 | C16.2 37.45,6.04 36.79,6.69 | v16.5,18 16.5,17.5 | R69.1 37.66,6.84 v37.5,7
  Bottom 0.5: R46.1 10.9,22.4 12,22.5 D19.A 14,21.5 16,19.5 16.8,19.5 D18.C v16.5,18 | v37.5,7 38,7.5
N$28  (1 unrouted)
  Bottom 0.406: 125,14.5 125,27 120.5,31.5 120.5,32.35 Q6.1
  Bottom 0.5: R56.1 37,34.9
N$29
  Bottom 0.5: 5M.2 RTOP1.1
N$30
  Bottom 0.406: R44.1 36,50.5 47,50.5 47,36 47.5,35.5 48.45,35.5 Q4.1
N$31  (1 unrouted)
  Bottom 0.5: Q7.1 116,31.85 118.5,29.5 120,29.5 123,26.5 123,15.5 | 38,37 35,38.5 R57.1
N$32
  Bottom 0.406: Q3.3 LED3.C
N$33
  Bottom 0.5: LED4.C 51,36.6 Q4.3
N$34
  Bottom 0.5: R19.1 52.6,64.2 D7.A
N$35
  Bottom 0.5: D7.C 56.8,64 D6.A
N$36
  Bottom 0.5: LED4.A R1.1
N$37
  Top 0.5: Q12.C 65.9,10 R30.2
N$38
  Bottom 0.5: D6.C 63.7,60.1 D5.A
N$39
  Bottom 0.5: R10.E 50.36,68.54 R19.2
N$40
  Bottom 0.5: R10.A 46.77,59.33 R20.2
N$41
  Bottom 0.406: D4.A 68.5,60.5 63,66 60.5,66 54.5,72 37.5,72 35.5,70.5 33.5,70.6 R4.1
N$42
  Bottom 0.5: D4.C D2.A
N$43
  Bottom 0.5: D2.C D1.A
N$44
  Bottom 0.5: R2.E 28.77,68.27 29,68.5 R4.2
N$45
  Bottom 0.5: R2.A 28.77,59.37 R5.2
N$46
  Bottom 0.5: R8.1 R2.S 31.77,65.5 C4.+
N$47
  Bottom 0.5: LED5.A R9.1
N$48
  Bottom 0.5: R22.1 41.4,67.1 42,66.5 C5.+ 43.23,66 R10.S
N$49
  Top 0.5: Q14.C 89.9,8.9 89,8 89,7 88,6 81,6 80,7 R35.2
N$50
  Top 0.5: Q15.B 54.54,18.54 52,16 52,8.4 53,7.4 R31.2 59,7.4 | 59,7.4 R30.1 | R23.2 58.9,7.5 59,7.4
N$51
  Top 0.5: Q16.B 104.54,13.96 106,12.5 | 106,12.5 107.69,12.5 Q10.1 108.9,11.29 R24.2 | R34.1 105,11.5 106,12.5
N$52
  Bottom 0.5: Q5.3 LED5.C
N$53  (via drill 0.6)
  Top 0.5: v75,11 71.9,11 R25.1 71.35,11.55 Q12.B
  Bottom 0.406: R7.2 119.5,48.1 119.5,50.5 128,50.5 128,11 76,11
  Bottom 0.5: v75,11 76,11
N$54
  Top 0.5: R31.1 56,12 57.25,12 Q9.1
N$55  (via drill 0.6)
  Top 0.5: v124.5,7.5 123.5,7 122.6,7.9 R27.1 119.6,7 118,7 117.6,7.4 Q13.B
  Bottom 0.5: R21.2 109.9,49.9 113.5,53.5 129.5,53.5 130,53 130,7.5 v124.5,7.5
N$56  (via drill 0.5 pad 1.5)
  Top 0.406: v18.5,16 18.5,15 18,14.5 17.5,14.69 Q18.1
  Bottom 0.406: R33.1 19.6,15.9 v18.5,16
N$57
  Top 0.5: R34.2 105,7.5 105.5,7 115,7 115.5,7.5 115.5,9.4 Q13.C
N$58
  Top 0.5: R32.1 37.79,13.9 Q19.1
N$59
  Top 0.406: Q17.B 79.54,14.46 81.5,12.5 82.69,12.5 Q11.1 82.72,10.18 R26.2
  Top 0.5: R35.1 80,11 81.5,12.5
N$60
  Bottom 0.5: R37.2 125.6,82.35 U$1.1
N$61
  Bottom 0.5: 125.5,72.75 U$1.2 122.75,70.5 C8.1
N$62
  Bottom 0.5: R38.2 R39.2
N$63
  Bottom 0.5: SNR.2 121.5,74.5 120.5,73.5 117,73.5 116,74.5 116,74.65 Q20.B
N$64  (1 unrouted)
  Bottom 0.5: 9.75,25.25 TR1.7 | 9,25 8.5,24.9 R46.2
  Bottom 1: 9,25 9.75,25.25
N$65
  Bottom 0.5: R12.E 19.04,68.54 20.5,70 20.5,70.9 R16.2
N$66  (via drill 0.6 pad 1.5)  (1 unrouted)
  Top 0.5: R32.2 33.5,16 32,16 | 32,16 v31.25,16 | R59.2 35.24,9.6 IC2.4 35,9.36 35,12 R60.1 33.1,14.9 32,16
  Bottom 0.406: R33.2 R51.1
  Bottom 0.5: R51.1 25.2,19.4 Q23.3 | R45.1 26.05,21 30,21 31,20 31,17 v31.25,16
N$67
  Top 0.5: C13.2 28,11 29,13 R60.2
N$68  (via drill 0.6)
  Top 0.5: Q19.2 v43.97,12.47 45.5,14 45.7,14 R47.2
N$71
  Bottom 0.5: Q22.3 19.5,22.1 R51.2
N$72  (via drill 0.6 pad 1.5)
  Top 0.5: 25.63,14.47 R48.2 26.8,16 v28,16
  Top 2: Q18.2 25.63,14.47
  Bottom 0.5: Q23.1 28.1,16.4 v28,16
N$73
  Bottom 0.5: 16.76,32.54 D16.A
  Bottom 1: R49.A 16.76,32.54
N$74
  Bottom 0.5: C9.1 9.35,16.6 TR1.9
N$76
  Bottom 0.5: D16.C 20.2,29.9 D12.A
N$77
  Bottom 0.5: D17.A 23.8,30 23,29.5 D12.C
N$78
  Bottom 1: R50.1 13.4,27.38 R49.E
N$79  (via drill 0.6 pad 1.5)  (1 unrouted)
  Top 0.5: 52,37.5 D11.A
  Bottom 0.5: v30.5,31 29.9,32 D17.C
N$80  (via drill 0.6 pad 1.5)  (1 unrouted)
  Top 0.5: R52.1 26,27.5 v26,25.75
  Bottom 0.5: R45.2 v26,25.75
N$81
  Bottom 0.406: R53.2 R54.1 57.25,50.9 Q24.B 57.45,51
N$82
  Bottom 0.406: LED3.A R53.1
N$96
  Top 0.5: C17.2 31.55,5.19 IC2.1
RB0  (via drill 0.6 pad 1.5)
  Top 0.406: v34.5,58 32.5,55.5 6,55.5 6,44 6.5,43 JP3.4
  Bottom 0.406: R22.2 36,58 v34.5,58
  Bottom 0.5: JP3.4 9.54,42.96 10.54,42.96 13,40.5 14.5,40.5 14.96,40.96 MIC.13
RB1  (via drill 0.6 pad 1.5)
  Top 0.406: v22.5,58 4,58 4,40.5 9.46,40.5 JP3.5
  Bottom 0.406: R8.2 22.5,65.5 v22.5,58
  Bottom 0.5: JP3.5 9.54,40.5 10,40.5 9.97,40.47 9.97,40.42 12.5,39 16,39 16.2,39.31 16.23,39.34 MIC.12
RB2  (via drill 0.6 pad 1.5)
  Top 0.406: v5,60.5 2,60.5 2,39 2.5,38 9.42,38 JP3.6
  Bottom 0.406: R14.2 4.5,61 v5,60.5
  Bottom 0.5: MIC.11 17.5,37.3 10.88,37.3 | 10.88,37.3 9.19,37.8 | JP3.6 10.88,37.3 | OK1.4 5.19,67.21 R14.2
RB4
  Bottom 0.5: MIC.3 16.23,46.27 17,45.5 24,45.5 25.5,43 JP6.4 28.5,43 29,43.5
RB5
  Bottom 0.5: MIC.2 14.96,45.54 16,44.5 23,44.5 23,40.5 JP6.3 27.54,41 R58.2
RC0
  Bottom 0.5: MIC.10 18.77,35.5 11.5,35.5 8.73,35.3 9.42,35.3 JP3.7 | R55.2 JP3.7 | R61.2 11,33.88 JP3.7
RC1
  Bottom 0.5: MIC.9 20.04,36.46 21,35.3 26.88,35.3 JP6.1 27.5,35.38 | 27.5,35.38 27.83,35.38 28.45,36 R56.2 | 27.5,35.38 27.62,35.5
RC2
  Bottom 0.5: MIC.8 21.31,38.99 22.1,38 25.08,38 JP6.2 27.58,38.5 R57.2
RC3
  Bottom 0.5: MIC.7 24.14,47.36 25.5,46 26,46 26.5,45.5 26.96,45.5 JP6.5 27.46,46 R42.2
RC4
  Bottom 0.5: MIC.6 20,47.4 20,49.5 24,49.5 25.42,48.08 JP6.6 27.42,48.5 R43.2
RC5
  Bottom 0.5: MIC.5 18.77,48.96 18.8,48.99 18.8,50.4 19.12,50.62 JP6.7 27.38,51 R44.2
S  (via drill 0.6)
  Top 0.5: v93.5,71.5 v94,52.5
  Bottom 0.5: X1.S 93.5,49.5 v94,52.5 | 15,77 14.5,75 13.5,74 13.08,74 OK1.2 12.58,74.5 12,74.5 11,73.5 R13.1 | 15,77 90,77 93.5,72 v93.5,71.5 | C2.- 15.73,74.77 15,77
T  (via drill 0.6)
  Top 0.5: v90.5,52.5 v90.5,65.5
  Bottom 0.5: D13.C 90,66 v90.5,65.5 | X1.T v90.5,52.5
U
  Top 0.5: 95.38,40.12 X1.U | Q17.C 85,24.96
  Top 3: 95.38,40.12 97,38.5 97,35.5 91.5,30 86.5,30 85,28 85,24.96 | Q11.3 Q17.C
V+
  Bottom 0.5: TPS1.5 12.45,5.1 R15.2 13.5,4.5 13,3.5 4.5,3.5 3.73,4.27 | MIC.1 12.97,48.08 JP3.2 5.68,48.08 C1.1 2.5,47.9 2,48 | 2,48 2,63.5 2,65.5 R14.1 | 2,8.23 2,48
  Bottom 1: 3.73,4.27 IC1.1 2,8.23
V-
  Bottom 0.5: TPS1.2 TPS1.3 8.5,8.15 8.5,8.5 8.55,8.55 C6.2 8.55,10.55 9,10.5 12.9,10.5 R17.1 13.9,9.9 13.5,9.5 R15.1
VSS  (via drill 0.8)  (35 unrouted)
  Top 0.5: OK1.3 6.23,74.27 8,72.5 8,62.5 11,59.5 | IC2.2 34,4.5 C17.1
  Bottom 0.5: MIC.14 13.69,42.81 11,45.5 | JP3.3 9.54,45.5
  Bottom 1.5: 9.54,45.5 11,45.5
  other vias: 68,41.5 73.5,32
  pour Bottom (isolate 2, rank 4): 1,59 17.5,63 48.5,63 60,54.5 79.5,54.5 82,49 96,49 96.5,55.5 96.5,64.5 106,90 146.5,89.5 146.5,1.5 0.5,2 0.5,54.5
  pour Top (isolate 2, rank 4, no thermals): 1.5,60 79,60 82,49 101.5,49 104,51.5 106,51.5 108,54 133,54.5 132.5,2 0.5,2 0.5,54.5
WIND
  Bottom 0.5: MIC.4 17.5,50 17.42,50.58 9,50.58 | 9,50.58 8.57,50.58 | 9.5,50.5 JP3.1 9.04,50.62 9,50.58
Y
  Top 0.5: 110,24.96 Q16.C Q10.3
  Top 3: X1.Y 99.62,45.88 110,35 110,24.96

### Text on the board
Top: MICHAEL5.net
